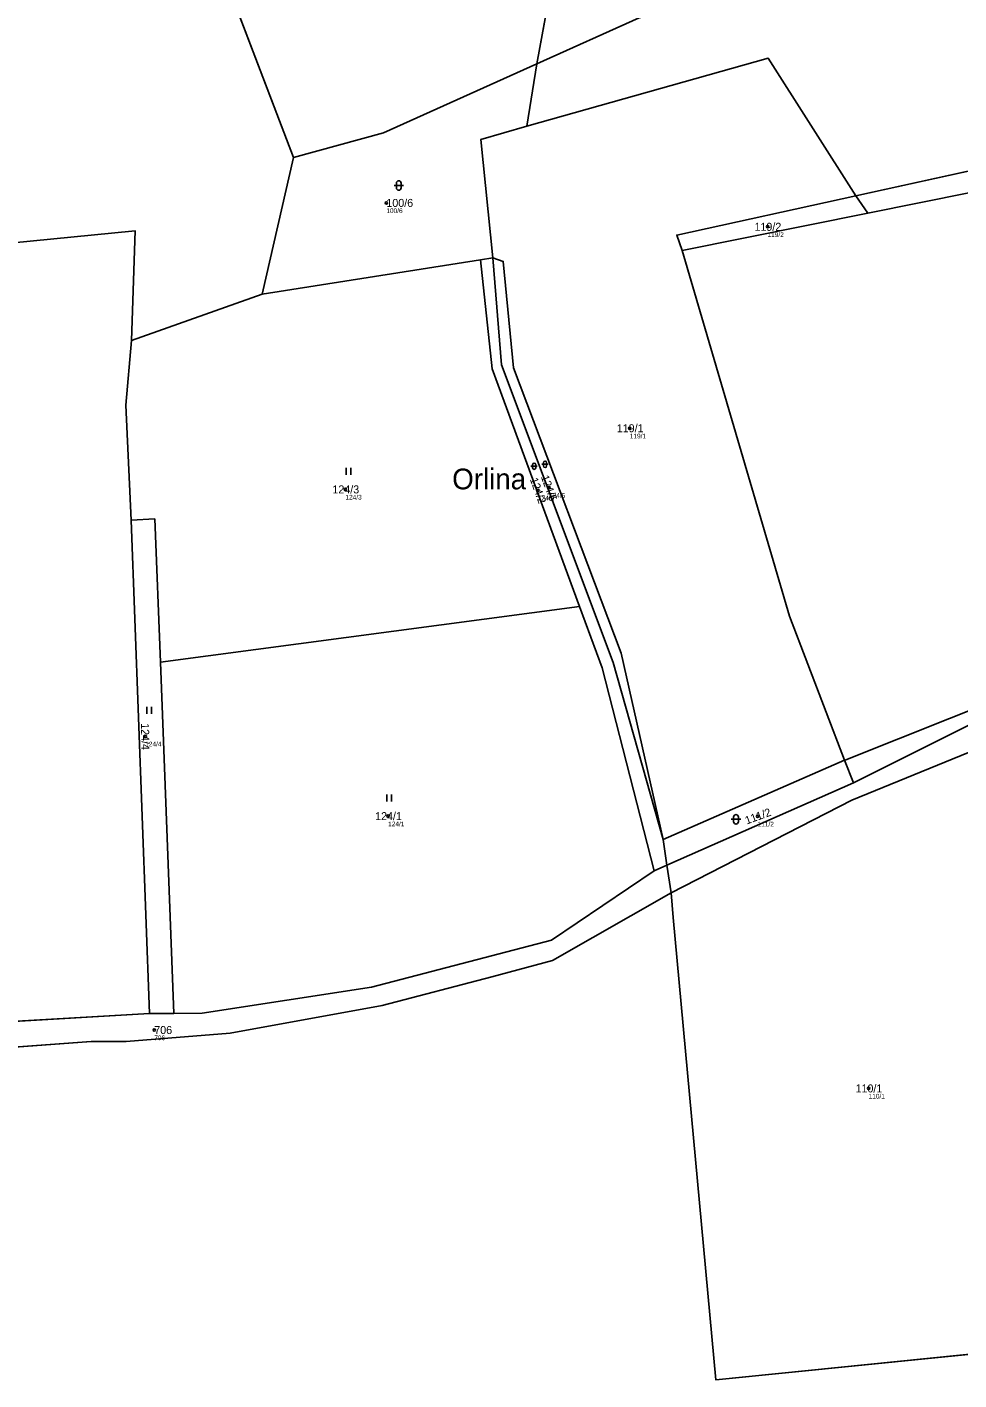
# Model space of a CAD drawing. Extents: x -767985 to -763816, y -1059600 to -1057360.
# Drawn here: x -765861.4 to -765663.5, y -1059600.5 to -1059313.1 of the extents above; entities that cross this region are included whole.
import ezdxf

# ---------------------------------------------------------------- set-up
doc = ezdxf.new("R2010")
doc.units = 0
for name, color, linetype in [('Definiční body', 7, 'Continuous'), ('Hranice parcel', 7, 'Continuous'), ('Parcelní čísla', 7, 'Continuous'), ('Polygon ku', 7, 'Continuous'), ('Polygon parcely', 7, 'Continuous'), ('Pop  PČ popisy', 7, 'Continuous'), ('Značky kultur', 7, 'Continuous')]:
    doc.layers.add(name, color=color, linetype=linetype)

msp = doc.modelspace()

# ---------------------------------------------------------------- linework, layer by layer
at = {"layer": 'Definiční body'}
for centre in [(-765785.08, -1059350.49994), (-765704.13, -1059355.56994), (-765733.38, -1059398.34994), (-765793.77, -1059411.33994), (-765752.88, -1059411.50994), (-765750.54, -1059410.97994), (-765836.29, -1059463.75994), (-765784.7, -1059480.72994), (-765706.24, -1059480.75994), (-765834.37, -1059526.14994), (-765682.67, -1059538.54994)]:
    msp.add_circle(centre, 0.25, dxfattribs=at)
at = {"layer": 'Hranice parcel'}
for p, q in [((-765753.13, -1059320.96), (-765737.42, -1059235.34)), ((-765821.58, -1059296.85), (-765804.78, -1059340.84)), ((-765753.13, -1059320.96), (-765755.22, -1059334.22)), ((-765685.39, -1059348.97), (-765604.89, -1059331.28)), ((-765804.78, -1059340.84), (-765811.49, -1059369.88)), ((-765682.86, -1059352.67), (-765685.39, -1059348.97)), ((-765722.26, -1059360.59), (-765682.86, -1059352.67)), ((-765811.49, -1059369.88), (-765765.06, -1059362.56)), ((-765765.06, -1059362.56), (-765762.49, -1059362.15)), ((-765811.49, -1059369.88), (-765839.22, -1059379.73)), ((-765839.27, -1059417.87), (-765835.4, -1059522.64)), ((-765744.03, -1059436.19), (-765833.08, -1059448.02)), ((-765833.08, -1059448.02), (-765830.22, -1059522.62)), ((-765726.31, -1059485.7), (-765687.8, -1059468.86)), ((-765687.8, -1059468.86), (-765685.91, -1059473.63)), ((-765685.91, -1059473.63), (-765725.5, -1059491.12)), ((-765725.5, -1059491.12), (-765726.31, -1059485.7)), ((-765728.23, -1059492.33), (-765725.5, -1059491.12)), ((-765725.5, -1059491.12), (-765724.61, -1059497.03)), ((-765724.61, -1059497.03), (-765749.83, -1059511.35)), ((-765724.15, -1059502.26), (-765724.61, -1059497.03)), ((-765715.1, -1059600.46), (-765724.15, -1059502.26)), ((-765786, -1059520.94), (-765818.27, -1059526.82)), ((-765901.54, -1059526.47), (-765835.4, -1059522.64)), ((-765835.4, -1059522.64), (-765830.22, -1059522.62)), ((-765847.8, -1059528.58), (-765905.89, -1059532.84)), ((-765715.1, -1059600.46), (-765622.83, -1059591.14))]:
    msp.add_line(p, q, dxfattribs=at)
for points in [[(-765676.47, -1059296.51), (-765731.36, -1059311.16), (-765753.13, -1059320.96)], [(-765755.22, -1059334.22), (-765703.99, -1059319.76), (-765685.39, -1059348.97)], [(-765804.78, -1059340.84), (-765785.71, -1059335.64), (-765753.13, -1059320.96)], [(-765604.89, -1059331.28), (-765605.79, -1059337.17), (-765682.86, -1059352.67)], [(-765762.49, -1059362.15), (-765765, -1059337), (-765755.22, -1059334.22)], [(-765722.26, -1059360.59), (-765723.41, -1059357.32), (-765685.39, -1059348.97)], [(-765839.22, -1059379.73), (-765838.46, -1059356.42), (-765909, -1059363.36)], [(-765687.8, -1059468.86), (-765699.49, -1059438.26), (-765722.26, -1059360.59)], [(-765765.06, -1059362.56), (-765762.6, -1059385.74), (-765744.03, -1059436.19)], [(-765762.49, -1059362.15), (-765760.26, -1059362.93), (-765758.09, -1059385.53), (-765735.21, -1059446.13), (-765726.31, -1059485.7)], [(-765726.31, -1059485.7), (-765736.91, -1059448.12), (-765760.61, -1059384.89), (-765762.49, -1059362.15)], [(-765839.22, -1059379.73), (-765840.41, -1059393.47), (-765839.27, -1059417.87)], [(-765495.16, -1059407.67), (-765521.97, -1059413.27), (-765534.98, -1059416.06), (-765569.38, -1059427.64), (-765591.82, -1059432.76), (-765635.48, -1059448.86), (-765654.34, -1059455.5), (-765687.53, -1059468.74), (-765687.8, -1059468.86)], [(-765495.16, -1059407.67), (-765528.35, -1059415.92), (-765654.28, -1059457.89), (-765685.91, -1059473.63)], [(-765839.27, -1059417.87), (-765834.25, -1059417.62), (-765833.08, -1059448.02)], [(-765728.23, -1059492.33), (-765739.23, -1059449.23), (-765744.03, -1059436.19)], [(-765648.31, -1059461.83), (-765686.22, -1059477.32), (-765724.61, -1059497.03)], [(-765830.22, -1059522.62), (-765824.17, -1059522.6), (-765788.23, -1059517.07), (-765750.04, -1059507.08), (-765728.23, -1059492.33)], [(-765749.83, -1059511.35), (-765762.68, -1059514.83), (-765786, -1059520.94)], [(-765818.27, -1059526.82), (-765840.31, -1059528.62), (-765847.8, -1059528.58)]]:
    msp.add_lwpolyline(points, dxfattribs=at)
at = {"layer": 'Polygon ku'}
for points in [[(-765749.83, -1059511.35), (-765724.61, -1059497.03), (-765724.15, -1059502.26), (-765715.1, -1059600.46), (-765622.83, -1059591.14), (-765481.89, -1059576.9), (-765353.92, -1059564.66), (-765346.49, -1059551.51), (-765345.46, -1059549.68), (-765344.55, -1059548.07), (-765342.22, -1059543.94), (-765337.09, -1059534.86), (-765245.77, -1059514.81)], [(-765905.89, -1059532.84), (-765847.8, -1059528.58), (-765840.31, -1059528.62), (-765818.27, -1059526.82), (-765786, -1059520.94), (-765762.68, -1059514.83), (-765749.83, -1059511.35)]]:
    msp.add_lwpolyline(points, dxfattribs=at)
at = {"layer": 'Polygon parcely'}
for points in [[(-765670.08, -1059108.79), (-765683.65, -1059090.74), (-765692.57, -1059066.29), (-765703.79, -1059106.19), (-765723.81, -1059167.16), (-765735.72, -1059224.57), (-765737.42, -1059235.34), (-765753.13, -1059320.96), (-765731.36, -1059311.16), (-765676.47, -1059296.51), (-765641.46, -1059132.18)], [(-765772.32, -1059241.76), (-765833.57, -1059267.51), (-765831.62, -1059275.23), (-765821.58, -1059296.85), (-765804.78, -1059340.84), (-765785.71, -1059335.64), (-765753.13, -1059320.96), (-765737.42, -1059235.34)], [(-765731.36, -1059311.16), (-765753.13, -1059320.96), (-765755.22, -1059334.22), (-765703.99, -1059319.76), (-765685.39, -1059348.97), (-765604.89, -1059331.28), (-765576.01, -1059324.94), (-765544.6, -1059320.89), (-765549.8, -1059309.9), (-765476.58, -1059297.67), (-765451.88, -1059293.53), (-765475.42, -1059277.39), (-765485.39, -1059270.59), (-765491.28, -1059271.62), (-765511.85, -1059275.21), (-765578.33, -1059300.08), (-765624.77, -1059308.36), (-765637.1, -1059286), (-765676.47, -1059296.51)], [(-765923.52, -1059341.99), (-765929.27, -1059363.85), (-765928.97, -1059365.28), (-765909, -1059363.36), (-765838.46, -1059356.42), (-765839.22, -1059379.73), (-765811.49, -1059369.88), (-765804.78, -1059340.84), (-765821.58, -1059296.85), (-765930.24, -1059310.62), (-765926.99, -1059316.27)], [(-765604.89, -1059331.28), (-765605.79, -1059337.17), (-765682.86, -1059352.67), (-765722.26, -1059360.59), (-765699.49, -1059438.26), (-765687.8, -1059468.86), (-765687.53, -1059468.74), (-765654.34, -1059455.5), (-765635.48, -1059448.86), (-765591.82, -1059432.76), (-765569.38, -1059427.64), (-765534.98, -1059416.06), (-765521.97, -1059413.27), (-765495.16, -1059407.67), (-765465.76, -1059402.69), (-765454.61, -1059402.71), (-765451.13, -1059378.41), (-765452.53, -1059353.68), (-765457.83, -1059330.49), (-765463.81, -1059320.99), (-765488.23, -1059315.68), (-765544.6, -1059320.89), (-765576.01, -1059324.94)], [(-765758.09, -1059385.53), (-765735.21, -1059446.13), (-765726.31, -1059485.7), (-765687.8, -1059468.86), (-765699.49, -1059438.26), (-765722.26, -1059360.59), (-765723.41, -1059357.32), (-765685.39, -1059348.97), (-765703.99, -1059319.76), (-765755.22, -1059334.22), (-765765, -1059337), (-765762.49, -1059362.15), (-765760.26, -1059362.93)], [(-765765.06, -1059362.56), (-765762.49, -1059362.15), (-765765, -1059337), (-765755.22, -1059334.22), (-765753.13, -1059320.96), (-765785.71, -1059335.64), (-765804.78, -1059340.84), (-765811.49, -1059369.88)], [(-765604.89, -1059331.28), (-765685.39, -1059348.97), (-765682.86, -1059352.67), (-765605.79, -1059337.17)], [(-765682.86, -1059352.67), (-765685.39, -1059348.97), (-765723.41, -1059357.32), (-765722.26, -1059360.59)], [(-765908.85, -1059391.43), (-765901.36, -1059435.18), (-765901.54, -1059526.47), (-765835.4, -1059522.64), (-765839.27, -1059417.87), (-765840.41, -1059393.47), (-765839.22, -1059379.73), (-765838.46, -1059356.42), (-765909, -1059363.36)], [(-765839.22, -1059379.73), (-765840.41, -1059393.47), (-765839.27, -1059417.87), (-765834.25, -1059417.62), (-765833.08, -1059448.02), (-765744.03, -1059436.19), (-765762.6, -1059385.74), (-765765.06, -1059362.56), (-765811.49, -1059369.88)], [(-765762.49, -1059362.15), (-765765.06, -1059362.56), (-765762.6, -1059385.74), (-765744.03, -1059436.19), (-765739.23, -1059449.23), (-765728.23, -1059492.33), (-765725.5, -1059491.12), (-765726.31, -1059485.7), (-765736.91, -1059448.12), (-765760.61, -1059384.89)], [(-765726.31, -1059485.7), (-765735.21, -1059446.13), (-765758.09, -1059385.53), (-765760.26, -1059362.93), (-765762.49, -1059362.15), (-765760.61, -1059384.89), (-765736.91, -1059448.12)], [(-765626.95, -1059453.1), (-765585.77, -1059439.07), (-765532.82, -1059421.19), (-765484.31, -1059409.54), (-765459.29, -1059405.8), (-765368.79, -1059406.82), (-765370.11, -1059403.19), (-765374.21, -1059402.91), (-765454.61, -1059402.71), (-765465.76, -1059402.69), (-765495.16, -1059407.67), (-765528.35, -1059415.92), (-765654.28, -1059457.89), (-765685.91, -1059473.63), (-765725.5, -1059491.12), (-765724.61, -1059497.03), (-765686.22, -1059477.32), (-765648.31, -1059461.83)], [(-765521.97, -1059413.27), (-765534.98, -1059416.06), (-765569.38, -1059427.64), (-765591.82, -1059432.76), (-765635.48, -1059448.86), (-765654.34, -1059455.5), (-765687.53, -1059468.74), (-765687.8, -1059468.86), (-765685.91, -1059473.63), (-765654.28, -1059457.89), (-765528.35, -1059415.92), (-765495.16, -1059407.67)], [(-765839.27, -1059417.87), (-765835.4, -1059522.64), (-765830.22, -1059522.62), (-765833.08, -1059448.02), (-765834.25, -1059417.62)], [(-765744.03, -1059436.19), (-765833.08, -1059448.02), (-765830.22, -1059522.62), (-765824.17, -1059522.6), (-765788.23, -1059517.07), (-765750.04, -1059507.08), (-765728.23, -1059492.33), (-765739.23, -1059449.23)], [(-765658.2, -1059533.35), (-765658.12, -1059527.9), (-765650.18, -1059512.85), (-765648.31, -1059461.83), (-765686.22, -1059477.32), (-765724.61, -1059497.03), (-765724.15, -1059502.26), (-765715.1, -1059600.46), (-765622.83, -1059591.14), (-765626.79, -1059538.56)], [(-765687.8, -1059468.86), (-765726.31, -1059485.7), (-765725.5, -1059491.12), (-765685.91, -1059473.63)], [(-765906.04, -1059526.74), (-765906.02, -1059529.36), (-765905.89, -1059532.84), (-765847.8, -1059528.58), (-765840.31, -1059528.62), (-765818.27, -1059526.82), (-765786, -1059520.94), (-765762.68, -1059514.83), (-765749.83, -1059511.35), (-765724.61, -1059497.03), (-765725.5, -1059491.12), (-765728.23, -1059492.33), (-765750.04, -1059507.08), (-765788.23, -1059517.07), (-765824.17, -1059522.6), (-765830.22, -1059522.62), (-765835.4, -1059522.64), (-765901.54, -1059526.47)]]:
    msp.add_lwpolyline(points, close=True, dxfattribs=at)
at = {"layer": 'Značky kultur'}
for p, q in [((-765782.941, -1059346.301), (-765782.941, -1059347.302)), ((-765781.939, -1059347.302), (-765781.939, -1059346.301)), ((-765783.441, -1059346.801), (-765781.439, -1059346.801)), ((-765793.641, -1059408.24), (-765793.641, -1059406.74)), ((-765792.64, -1059408.24), (-765792.64, -1059406.74)), ((-765754.371, -1059406.431), (-765753.029, -1059406.431)), ((-765754.035, -1059406.095), (-765754.035, -1059406.766)), ((-765753.365, -1059406.766), (-765753.365, -1059406.095)), ((-765752.051, -1059406.011), (-765750.709, -1059406.011)), ((-765751.715, -1059405.675), (-765751.715, -1059406.346)), ((-765751.045, -1059406.346), (-765751.045, -1059405.675)), ((-765835.971, -1059459), (-765835.971, -1059457.5)), ((-765834.97, -1059459), (-765834.97, -1059457.5)), ((-765784.971, -1059477.65), (-765784.971, -1059476.15)), ((-765783.97, -1059477.65), (-765783.97, -1059476.15)), ((-765711.831, -1059481.401), (-765709.829, -1059481.401)), ((-765711.331, -1059480.901), (-765711.331, -1059481.902)), ((-765710.329, -1059481.902), (-765710.329, -1059480.901))]:
    msp.add_line(p, q, dxfattribs=at)
for centre, radius, start, end in [((-765782.44, -1059346.3009), 0.5, 0, 180), ((-765782.44, -1059347.3009), 0.5, 180, 359.9878861), ((-765753.7, -1059406.0956), 0.335, 0, 180), ((-765753.7, -1059406.7656), 0.335, 180, 359.9878861), ((-765751.38, -1059405.6756), 0.335, 0, 180), ((-765751.38, -1059406.3456), 0.335, 180, 359.9878861), ((-765710.83, -1059480.9009), 0.5, 0, 180), ((-765710.83, -1059481.9009), 0.5, 180, 359.9878861)]:
    msp.add_arc(centre, radius, start, end, dxfattribs=at)

# ---------------------------------------------------------------- texts
at = {"layer": 'Definiční body'}
for s, p in [('100/6', (-765785.08, -1059352.656)), ('119/2', (-765704.13, -1059357.726)), ('119/1', (-765733.38, -1059400.506)), ('124/3', (-765793.77, -1059413.496)), ('124/5', (-765750.54, -1059413.136)), ('124/2', (-765752.88, -1059413.666)), ('124/4', (-765836.29, -1059465.916)), ('124/1', (-765784.7, -1059482.886)), ('111/2', (-765706.24, -1059482.916)), ('706', (-765834.37, -1059528.306)), ('110/1', (-765682.67, -1059540.706))]:
    msp.add_text(s, height=0.999996, dxfattribs=at).set_placement(p)
at = {"layer": 'Parcelní čísla'}
for s, p in [('100/6', (-765785.08, -1059351.35)), ('119/2', (-765706.903, -1059356.42)), ('119/1', (-765736.153, -1059399.2)), ('124/3', (-765796.543, -1059412.19)), ('124/1', (-765787.473, -1059481.58)), ('706', (-765834.37, -1059527)), ('110/1', (-765685.443, -1059539.4))]:
    msp.add_text(s, height=1.699998, dxfattribs=at).set_placement(p)
for s, rotation, p in [('124/2', 290, (-765754.627, -1059409.194)), ('124/5', 290, (-765752.287, -1059408.664)), ('124/4', 271, (-765837.188, -1059461.001)), ('111/2', 20, (-765708.555, -1059482.507))]:
    msp.add_text(s, height=1.699998, rotation=rotation, dxfattribs=at).set_placement(p)
at = {"layer": 'Pop  PČ popisy'}
msp.add_text('Orlina', height=4.399998, dxfattribs=at).set_placement((-765771.1, -1059411.32))

doc.saveas('drawing.dxf')
